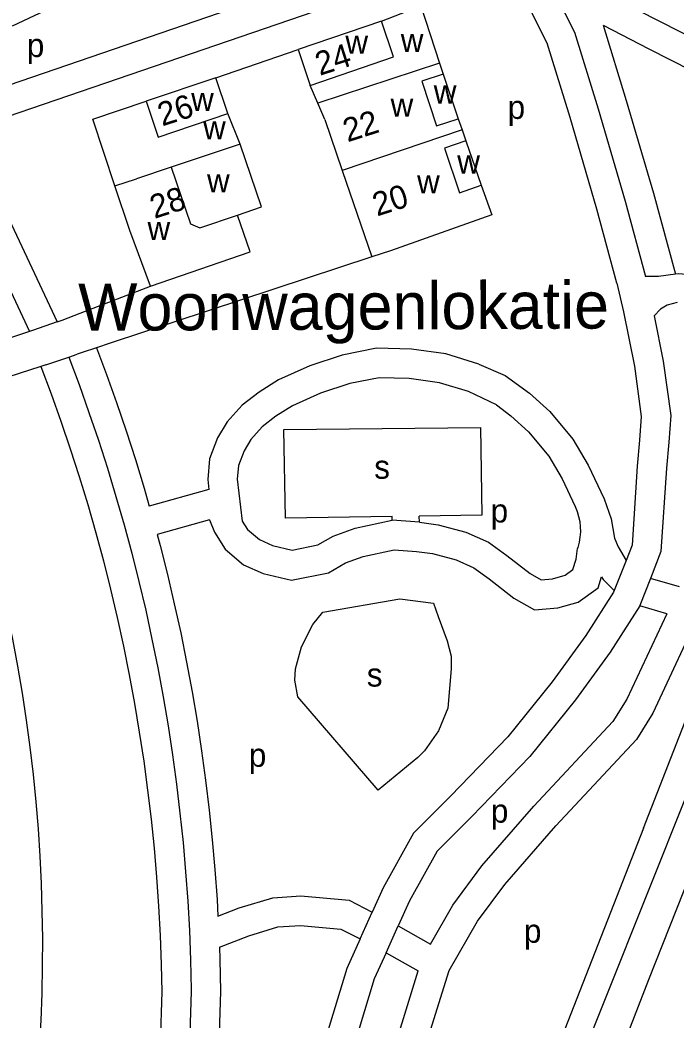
# Model space of a CAD drawing. Extents: x 157794 to 159375, y 380877 to 382306.
# Drawn here: x 159007.2 to 159118.9, y 381561.1 to 381731.3 of the extents above; entities that cross this region are included whole.
import ezdxf

# ---------------------------------------------------------------- set-up
doc = ezdxf.new("R2010")
doc.units = 0
for name, color, linetype in [('BLT_Basislijn', 7, 'Continuous'), ('BLT_Bebouwing', 7, 'Continuous'), ('BLT_Centroide', 7, 'Continuous'), ('BLT_Huisnummer', 7, 'Continuous'), ('BLT_Terrein_beschrifting', 7, 'Continuous')]:
    doc.layers.add(name, color=color, linetype=linetype)

msp = doc.modelspace()

# ---------------------------------------------------------------- linework, layer by layer
at = {"layer": 'BLT_Basislijn'}
for p, q in [((159073.46, 381743.61), (158994.46, 381716.52)), ((159005.91, 381730.36), (159018.4, 381736.22)), ((159068.77, 381731.14), (159075.44, 381733.75)), ((159040.55, 381721.52), (159054.57, 381726.29)), ((159057.95, 381717.18), (159056.64, 381720.2)), ((159044.73, 381710.22), (159042.61, 381715.44)), ((159059.12, 381714.38), (159062.09, 381705.72)), ((159044.73, 381710.22), (159032.93, 381706.29)), ((159048.31, 381699.54), (159044.73, 381710.22)), ((159062.09, 381705.72), (159067.14, 381691.02)), ((159044.22, 381698.13), (159048.31, 381699.54)), ((159115.95, 381687.72), (159113.74, 381687.68)), ((159118.81, 381688.1), (159115.95, 381687.72)), ((159117.44, 381682.83), (159116.29, 381682.14)), ((159119.12, 381683.25), (159117.44, 381682.83)), ((159116.29, 381682.14), (159115.22, 381680.99)), ((159013.56, 381679.97), (159009.34, 381678.54)), ((159008.8, 381678.36), (158992.46, 381672.87)), ((159009.34, 381678.54), (159008.8, 381678.36)), ((159022.56, 381676.33), (159020.25, 381675.57)), ((159011.61, 381672.68), (159015.5, 381673.99)), ((159015.5, 381673.99), (159016.97, 381674.48)), ((159017.81, 381674.76), (159016.97, 381674.48)), ((159020.25, 381675.57), (159017.81, 381674.76)), ((159010.76, 381672.41), (158994.49, 381667.18)), ((159011.61, 381672.68), (159010.76, 381672.41)), ((159052.11, 381661.65), (159085.65, 381662.02)), ((159085.65, 381662.02), (159085.84, 381647.08)), ((159052.4, 381646.59), (159052.11, 381661.65)), ((159112.72, 381659.85), (159112.32, 381655.41)), ((159117.71, 381659.49), (159117.31, 381655.08)), ((159070.59, 381646.85), (159052.4, 381646.59)), ((159070.6, 381646.22), (159070.59, 381646.85)), ((159085.84, 381647.08), (159075.17, 381646.92)), ((159075.26, 381645.88), (159075.17, 381646.92)), ((159075.26, 381645.88), (159070.6, 381646.22)), ((159110.41, 381639.41), (159108.4, 381634.28)), ((159119.5, 381634.92), (159114.58, 381636.35)), ((159058.77, 381630.62), (159071.9, 381632.87)), ((159071.9, 381632.87), (159077.63, 381632.15)), ((159077.63, 381632.15), (159078.43, 381629.86)), ((159117.36, 381630.34), (159112.74, 381631.68)), ((159057.09, 381628.49), (159058.77, 381630.62)), ((159078.43, 381629.86), (159079.97, 381625.74)), ((159055.12, 381624.7), (159057.09, 381628.49)), ((159054.12, 381620.95), (159055.12, 381624.7)), ((159079.97, 381625.74), (159080.63, 381623.11)), ((159080.63, 381623.11), (159080.65, 381620.95)), ((159054.03, 381619.03), (159054.12, 381620.95)), ((159080.65, 381620.95), (159080.07, 381614.27)), ((159054.52, 381616.19), (159054.03, 381619.03)), ((159068.21, 381600.34), (159054.52, 381616.19)), ((159080.07, 381614.27), (159078.49, 381610.4)), ((159078.49, 381610.4), (159076.09, 381606.98)), ((159074.95, 381605.86), (159068.21, 381600.34)), ((159076.09, 381606.98), (159074.95, 381605.86)), ((159065.13, 381575), (159067.2, 381579.56)), ((159069.55, 381572.64), (159071.62, 381577.21)), ((159031.37, 381565.99), (159030.38, 381537.62)), ((159036.37, 381566.07), (159035.37, 381537.28)), ((159041.37, 381566.09), (159040.37, 381537.03))]:
    msp.add_line(p, q, dxfattribs=at)
for points in [[(159108.87, 381686.54), (159105.46, 381699.16), (159100.87, 381714.75), (159096.96, 381727.42), (159090, 381741.34), (159089.57, 381741.73), (159089.09, 381742.06), (159088.58, 381742.33), (159088.02, 381742.52), (159087.45, 381742.63), (159086.87, 381742.66), (159086.29, 381742.62), (159085.72, 381742.49), (159085.49, 381742.42), (159084.45, 381742.09), (158998.68, 381712.68), (159004.91, 381698.37), (159013.56, 381679.97)], [(159102.86, 381737.9), (159116.59, 381730.9), (159127, 381725.59), (159133.66, 381723.61), (159143.59, 381722.37), (159147.4, 381722.17)], [(159098.32, 381735.79), (159101.61, 381729.28), (159105.66, 381716.2), (159110.27, 381700.52), (159113.74, 381687.68)], [(159075.44, 381733.75), (159078.64, 381724.01)], [(159106.49, 381730.44), (159114.32, 381726.44), (159125.13, 381720.93), (159132.63, 381718.7), (159143.15, 381717.38), (159147.46, 381717.16)], [(159106.49, 381730.44), (159110.45, 381717.64), (159115.08, 381701.87), (159118.81, 381688.1)], [(159078.64, 381724.01), (159057.95, 381717.18)], [(159078.64, 381724.01), (159079.26, 381722.11)], [(159023.38, 381703.11), (159019.64, 381714.46), (159028.69, 381717.5)], [(159059.12, 381714.38), (159057.95, 381717.18)], [(159081.84, 381714.54), (159082.48, 381712.67)], [(159082.48, 381712.67), (159062.09, 381705.72)], [(159082.48, 381712.67), (159083.13, 381710.78)], [(158993.95, 381711), (159000.36, 381696.3), (159008.8, 381678.36)], [(159085.73, 381703.23), (159087.56, 381698.18), (159070.28, 381692.05)], [(159067.14, 381691.02), (159022.56, 381676.33)], [(159070.28, 381692.05), (159067.14, 381691.02)], [(159123.06, 381687.8), (159119.39, 381688.18), (159118.81, 381688.1)], [(159013.56, 381679.97), (159014.41, 381680.26), (159017.48, 381681.45), (159029.44, 381686.03)], [(159108.87, 381686.54), (159109.99, 381681.66), (159111.83, 381672.44), (159113.01, 381663.88), (159112.72, 381659.85)], [(159115.22, 381680.99), (159116.76, 381673.27), (159118.04, 381664.05), (159117.71, 381659.49)], [(159015.5, 381673.99), (159017.26, 381669.31), (159018.95, 381664.59), (159020.56, 381659.85), (159022.09, 381655.09), (159023.55, 381650.3), (159024.93, 381645.48), (159026.23, 381640.65), (159027.46, 381635.79), (159028.61, 381630.92), (159029.68, 381626.03), (159030.67, 381621.12), (159031.59, 381616.2), (159032.42, 381611.26), (159033.18, 381606.31), (159033.85, 381601.35), (159034.45, 381596.38), (159034.97, 381591.4), (159035.41, 381586.41), (159035.77, 381581.42), (159036.05, 381576.42), (159036.24, 381571.41), (159036.36, 381566.41), (159036.37, 381566.07)], [(159020.25, 381675.57), (159021.96, 381671.03), (159023.67, 381666.24), (159025.3, 381661.42), (159026.86, 381656.58), (159028.34, 381651.71), (159029.23, 381648.63)], [(159085.36, 381672.78), (159079.71, 381674.53), (159073.89, 381675.33), (159067.94, 381675.48), (159062.1, 381674.32), (159056.57, 381672.53), (159051.23, 381670.13), (159047.92, 381668.03), (159045.03, 381665.79), (159042.51, 381662.98), (159040.85, 381660.25), (159039.48, 381656.68), (159039.19, 381653.14), (159039.38, 381651.48), (159029.23, 381648.63)], [(159113.39, 381593.87), (159144.77, 381674.12)], [(159010.76, 381672.41), (159012.51, 381667.76), (159014.18, 381663.08), (159015.78, 381658.38), (159017.3, 381653.65), (159018.75, 381648.9), (159020.12, 381644.12), (159021.41, 381639.33), (159022.63, 381634.51), (159023.76, 381629.68), (159024.82, 381624.82), (159025.8, 381619.96), (159026.71, 381615.07), (159027.53, 381610.17), (159028.28, 381605.26), (159028.94, 381600.34), (159029.53, 381595.41), (159030.04, 381590.47), (159030.46, 381585.52), (159030.81, 381580.56), (159031.08, 381575.6), (159031.27, 381570.64), (159031.37, 381565.99)], [(159085.36, 381672.78), (159089.85, 381670.84), (159093.99, 381667.87), (159097.42, 381664.76), (159101.35, 381660.02), (159103.96, 381655.61), (159106.68, 381649.86), (159107.86, 381646.48), (159108.46, 381643.18), (159109.06, 381641.73), (159110.41, 381639.41)], [(159149.36, 381672.32), (159141.87, 381652.41), (159100, 381547.62), (159098.42, 381543.64)], [(159088.36, 381665.87), (159083.56, 381668.11), (159078.63, 381669.63), (159073.49, 381670.34), (159068.37, 381670.46), (159063.36, 381669.47), (159058.36, 381667.85), (159053.61, 381665.72), (159050.8, 381663.94), (159048.45, 381662.11), (159046.54, 381659.99), (159045.36, 381658.04), (159044.4, 381655.55), (159044.21, 381653.22), (159045.06, 381646.07)], [(159088.36, 381665.87), (159090.79, 381664.02), (159093.8, 381661.29), (159097.24, 381657.13), (159099.54, 381653.26), (159101.76, 381648.56)], [(158996.23, 381661.94), (158997.71, 381657.52), (158999.11, 381653.08), (159000.44, 381648.62), (159001.69, 381644.13), (159002.86, 381639.62), (159003.96, 381635.1), (159004.97, 381630.55), (159005.91, 381625.99), (159006.77, 381621.42), (159007.56, 381616.83), (159008.26, 381612.22), (159008.88, 381607.61), (159009.43, 381602.98), (159009.89, 381598.35), (159010.28, 381593.71), (159010.58, 381589.06), (159010.81, 381584.41), (159010.95, 381579.75), (159011.02, 381575.1), (159011.01, 381570.44), (159010.91, 381565.79), (159010.74, 381561.13), (159010.55, 381557.62)], [(159112.32, 381655.41), (159111.43, 381642), (159110.41, 381639.41)], [(159117.31, 381655.08), (159116.36, 381640.89), (159114.58, 381636.35)], [(159101.76, 381648.56), (159102.09, 381647.73), (159102.34, 381646.88), (159102.52, 381646.01), (159102.62, 381645.13), (159102.63, 381644.24), (159102.57, 381643.36), (159102.43, 381642.48), (159102.21, 381641.62), (159102.14, 381641.41)], [(159130.84, 381646.73), (159128.38, 381642.11), (159114.96, 381613.41), (159112.17, 381608.95)], [(159039.46, 381646.31), (159030.56, 381643.81)], [(159039.46, 381646.31), (159040.31, 381644.22), (159042.15, 381641.32), (159045.29, 381638.65), (159048.64, 381637.18), (159053.46, 381636.06), (159059.74, 381637.31), (159062.62, 381638.99), (159065.64, 381640.04), (159070.95, 381641.18), (159074.75, 381640.91), (159077.47, 381640.55), (159081.47, 381639.48), (159084.5, 381638.14), (159087.11, 381636.25), (159091.3, 381632.97), (159094.84, 381631.02), (159098.79, 381631.32), (159102.25, 381632.3), (159105.65, 381634.75), (159106.24, 381636.63)], [(159045.06, 381646.07), (159045.97, 381644.64), (159047.97, 381642.94), (159050.23, 381641.94), (159053.54, 381641.17), (159057.95, 381642.05), (159060.52, 381643.55), (159064.29, 381644.87), (159070.6, 381646.22)], [(159075.26, 381645.88), (159078.44, 381645.47), (159083.14, 381644.2), (159087, 381642.5), (159090.11, 381640.25), (159094.06, 381637.15), (159095.95, 381636.12), (159097.91, 381636.27), (159100.04, 381636.87), (159101.37, 381637.83), (159101.93, 381639.62), (159102.14, 381641.41)], [(159030.56, 381643.81), (159031.07, 381641.91), (159032.32, 381636.98), (159033.48, 381632.03), (159034.57, 381627.06), (159035.58, 381622.07), (159036.51, 381617.07), (159037.36, 381612.05), (159038.13, 381607.03), (159038.81, 381601.99), (159039.42, 381596.93), (159039.95, 381591.87), (159040.39, 381586.81), (159040.76, 381581.73), (159040.92, 381578.87)], [(159106.24, 381636.63), (159106.51, 381636.17), (159108.4, 381634.28)], [(159114.58, 381636.35), (159112.76, 381631.72), (159112.74, 381631.68)], [(159108.4, 381634.28), (159108.29, 381634), (159103.56, 381626.61), (159097.82, 381618.75), (159090.27, 381609.39), (159080.56, 381599.36), (159074.2, 381593), (159069.08, 381583.71), (159067.2, 381579.56)], [(159112.74, 381631.68), (159107.69, 381623.79), (159101.79, 381615.71), (159094.02, 381606.07), (159084.13, 381595.86), (159078.24, 381589.96), (159073.55, 381581.47), (159071.62, 381577.21)], [(159117.36, 381630.34), (159110.56, 381615.8), (159108.19, 381612.02)], [(159077.12, 381574.14), (159080.94, 381580.77), (159085.88, 381587.43), (159094.72, 381597.62), (159108.19, 381612.02)], [(159036.36, 381477.61), (159040.23, 381477.84), (159045.36, 381479.09), (159049.18, 381481.13), (159052.52, 381484.54), (159054.98, 381488.78), (159058.34, 381497.19), (159066.67, 381519.12), (159069.91, 381532.4), (159071.39, 381541.15), (159080.3, 381569.64), (159085.12, 381578.02), (159089.78, 381584.29), (159098.44, 381594.27), (159112.17, 381608.95)], [(159127.48, 381601.4), (159114.23, 381568.04), (159104.74, 381543.62)], [(159113.39, 381593.87), (159100, 381559.65), (159094.31, 381545.18)], [(159040.92, 381578.87), (159044.53, 381580.29), (159050.24, 381581.99), (159055.05, 381582.33), (159063.27, 381581.58), (159067.2, 381579.56)], [(159041.16, 381573.6), (159046.16, 381575.55), (159051.14, 381577.04), (159055, 381577.31), (159061.85, 381576.69), (159065.13, 381575)], [(159071.62, 381577.21), (159077.12, 381574.14)], [(159065.13, 381575), (159062.85, 381569.99), (159058.49, 381555.65), (159053.86, 381536.2), (159051.72, 381524.58), (159049.29, 381515.13), (159048.08, 381509.99), (159046.35, 381504.53), (159045.84, 381503.67), (159044.1, 381502.37), (159041.2, 381501.4), (159039.65, 381501.4)], [(159041.16, 381573.6), (159041.24, 381571.57), (159041.37, 381566.09)], [(159069.55, 381572.64), (159067.54, 381568.22), (159063.32, 381554.35), (159058.76, 381535.17), (159056.61, 381523.5), (159054.14, 381513.94), (159052.9, 381508.66), (159050.95, 381502.47), (159049.62, 381500.26), (159046.46, 381497.89), (159042.01, 381496.4), (159039.86, 381496.4), (159037.61, 381496.23)], [(159069.55, 381572.64), (159075.04, 381569.57)], [(159036.7, 381482.64), (159039.49, 381482.81), (159043.56, 381483.8), (159046.14, 381485.18), (159048.51, 381487.6), (159050.47, 381490.97), (159053.68, 381499.01), (159058.85, 381512.64), (159061.88, 381520.61), (159065.01, 381533.42), (159066.52, 381542.32), (159069.42, 381551.61), (159072.27, 381560.74), (159075.04, 381569.57)]]:
    msp.add_lwpolyline(points, dxfattribs=at)
at = {"layer": 'BLT_Bebouwing'}
for p, q in [((159068.77, 381731.14), (159054.57, 381726.29)), ((159054.57, 381726.29), (159056.64, 381720.2)), ((159040.55, 381721.52), (159028.69, 381717.5)), ((159042.61, 381715.44), (159040.55, 381721.52)), ((159032.93, 381706.29), (159027.03, 381704.3)), ((159029.44, 381686.03), (159025.9, 381695.51))]:
    msp.add_line(p, q, dxfattribs=at)
for points in [[(159056.64, 381720.2), (159070.84, 381725.06), (159068.77, 381731.14)], [(159079.26, 381722.11), (159075.62, 381720.91), (159078.14, 381713.31), (159081.84, 381714.54)], [(159079.26, 381722.11), (159081.84, 381714.54)], [(159028.69, 381717.5), (159030.75, 381711.42), (159042.61, 381715.44)], [(159083.13, 381710.78), (159079.52, 381709.55), (159082.05, 381701.92), (159085.73, 381703.23)], [(159083.13, 381710.78), (159085.73, 381703.23)], [(159032.93, 381706.29), (159036.23, 381696.66), (159037.82, 381695.99), (159044.22, 381698.13)], [(159023.38, 381703.11), (159027.03, 381704.3)], [(159025.9, 381695.51), (159023.38, 381703.11)], [(159029.44, 381686.03), (159046.42, 381691.88), (159044.22, 381698.13)]]:
    msp.add_lwpolyline(points, dxfattribs=at)

# ---------------------------------------------------------------- texts
at = {"layer": 'BLT_Centroide'}
for s, p in [('w', (159062.62, 381725.59)), ('w', (159072.05, 381725.89)), ('p', (159008.38, 381725.04)), ('w', (159077.67, 381717.12)), ('w', (159036.35, 381715.87)), ('w', (159070.32, 381714.88)), ('p', (159090.25, 381714.51)), ('w', (159038.39, 381711.05)), ('w', (159081.67, 381705.22)), ('w', (159039.06, 381702.03)), ('w', (159074.83, 381701.84)), ('w', (159028.92, 381693.91)), ('s', (159067.53, 381653.29)), ('p', (159087.36, 381645.85)), ('s', (159066.27, 381617.94)), ('p', (159046.18, 381604.29)), ('p', (159087.4, 381594.79)), ('p', (159093.03, 381574.36))]:
    msp.add_text(s, height=4, dxfattribs=at).set_placement(p)
at = {"layer": 'BLT_Huisnummer'}
for s, p in [('24', (159058.25, 381721.83)), ('26', (159031.42, 381713.22)), ('22', (159062.98, 381710.51)), ('28', (159030.1, 381697.49)), ('20', (159068.01, 381697.9))]:
    msp.add_text(s, height=4, rotation=17.7249, dxfattribs=at).set_placement(p)
at = {"layer": 'BLT_Terrein_beschrifting'}
msp.add_text('Woonwagenlokatie', height=8, rotation=0.244, dxfattribs=at).set_placement((159017.14, 381678.47))

doc.saveas('drawing.dxf')
